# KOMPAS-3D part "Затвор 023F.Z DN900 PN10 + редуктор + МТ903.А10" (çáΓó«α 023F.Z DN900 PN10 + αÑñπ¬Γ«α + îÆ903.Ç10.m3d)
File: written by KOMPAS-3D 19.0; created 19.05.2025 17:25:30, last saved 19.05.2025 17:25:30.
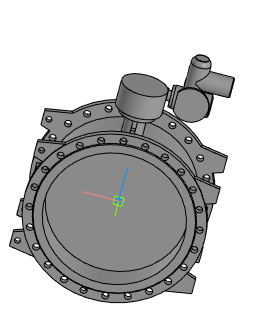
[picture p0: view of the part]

Document properties: Полное имя файла: Затвор 023F.Z DN900 PN10 + редуктор + МТ903.А10.a3d

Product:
- Part/product: Затвор 023F.Z DN900 PN10 + редуктор + МТ903.А10
    Масса: 861.345

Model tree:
1. Операция без истории:1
